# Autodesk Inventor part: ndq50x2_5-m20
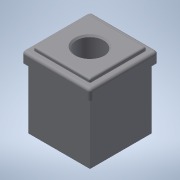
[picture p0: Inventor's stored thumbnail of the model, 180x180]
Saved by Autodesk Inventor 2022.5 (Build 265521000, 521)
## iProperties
Created: 2016-12
Part Number: ndq50x2_5-m20
Material: 一般
Document SubType Name: Modeling
Designer: imaocorp
Density: 1 g/cm^3
Appearance: 既定
Author: imaocorp
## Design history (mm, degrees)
node "ndq50x2_5-m20.x_t1"
node "ndq50x2_5-m20"
node "Base1"
